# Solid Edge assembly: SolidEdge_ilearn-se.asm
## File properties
Author: Administrator
Template: Normal.asm
Last saved by: Administrator
Revision: 9
Application: Solid Edge
Agile_Description: iLearn Assembly
Modeled_By: L. Conard
Part_Number: ITEM-SE-00001
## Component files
3DSolidEdge_top.par
3DSolidEdge_board.par
3DSolidEdge_bottom.par
3DSolidEdge_stop_button.par
3DSolidEdge_go_button.par
3DSolidEdge_arrow.par
3DSolidEdge_screen.par
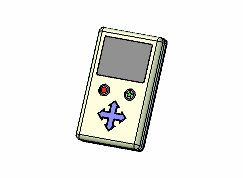
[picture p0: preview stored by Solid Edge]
